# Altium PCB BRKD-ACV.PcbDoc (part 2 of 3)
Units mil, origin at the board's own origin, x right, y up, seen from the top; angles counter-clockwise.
Board outline 5708.66 x 3740.16 mil, 4 copper layers (L1-TOP, L2-GND, L3-PWR, L4-BOT), stack 61.722 mil thick; 171 components, 263 nets, 918 pads, 406 vias.
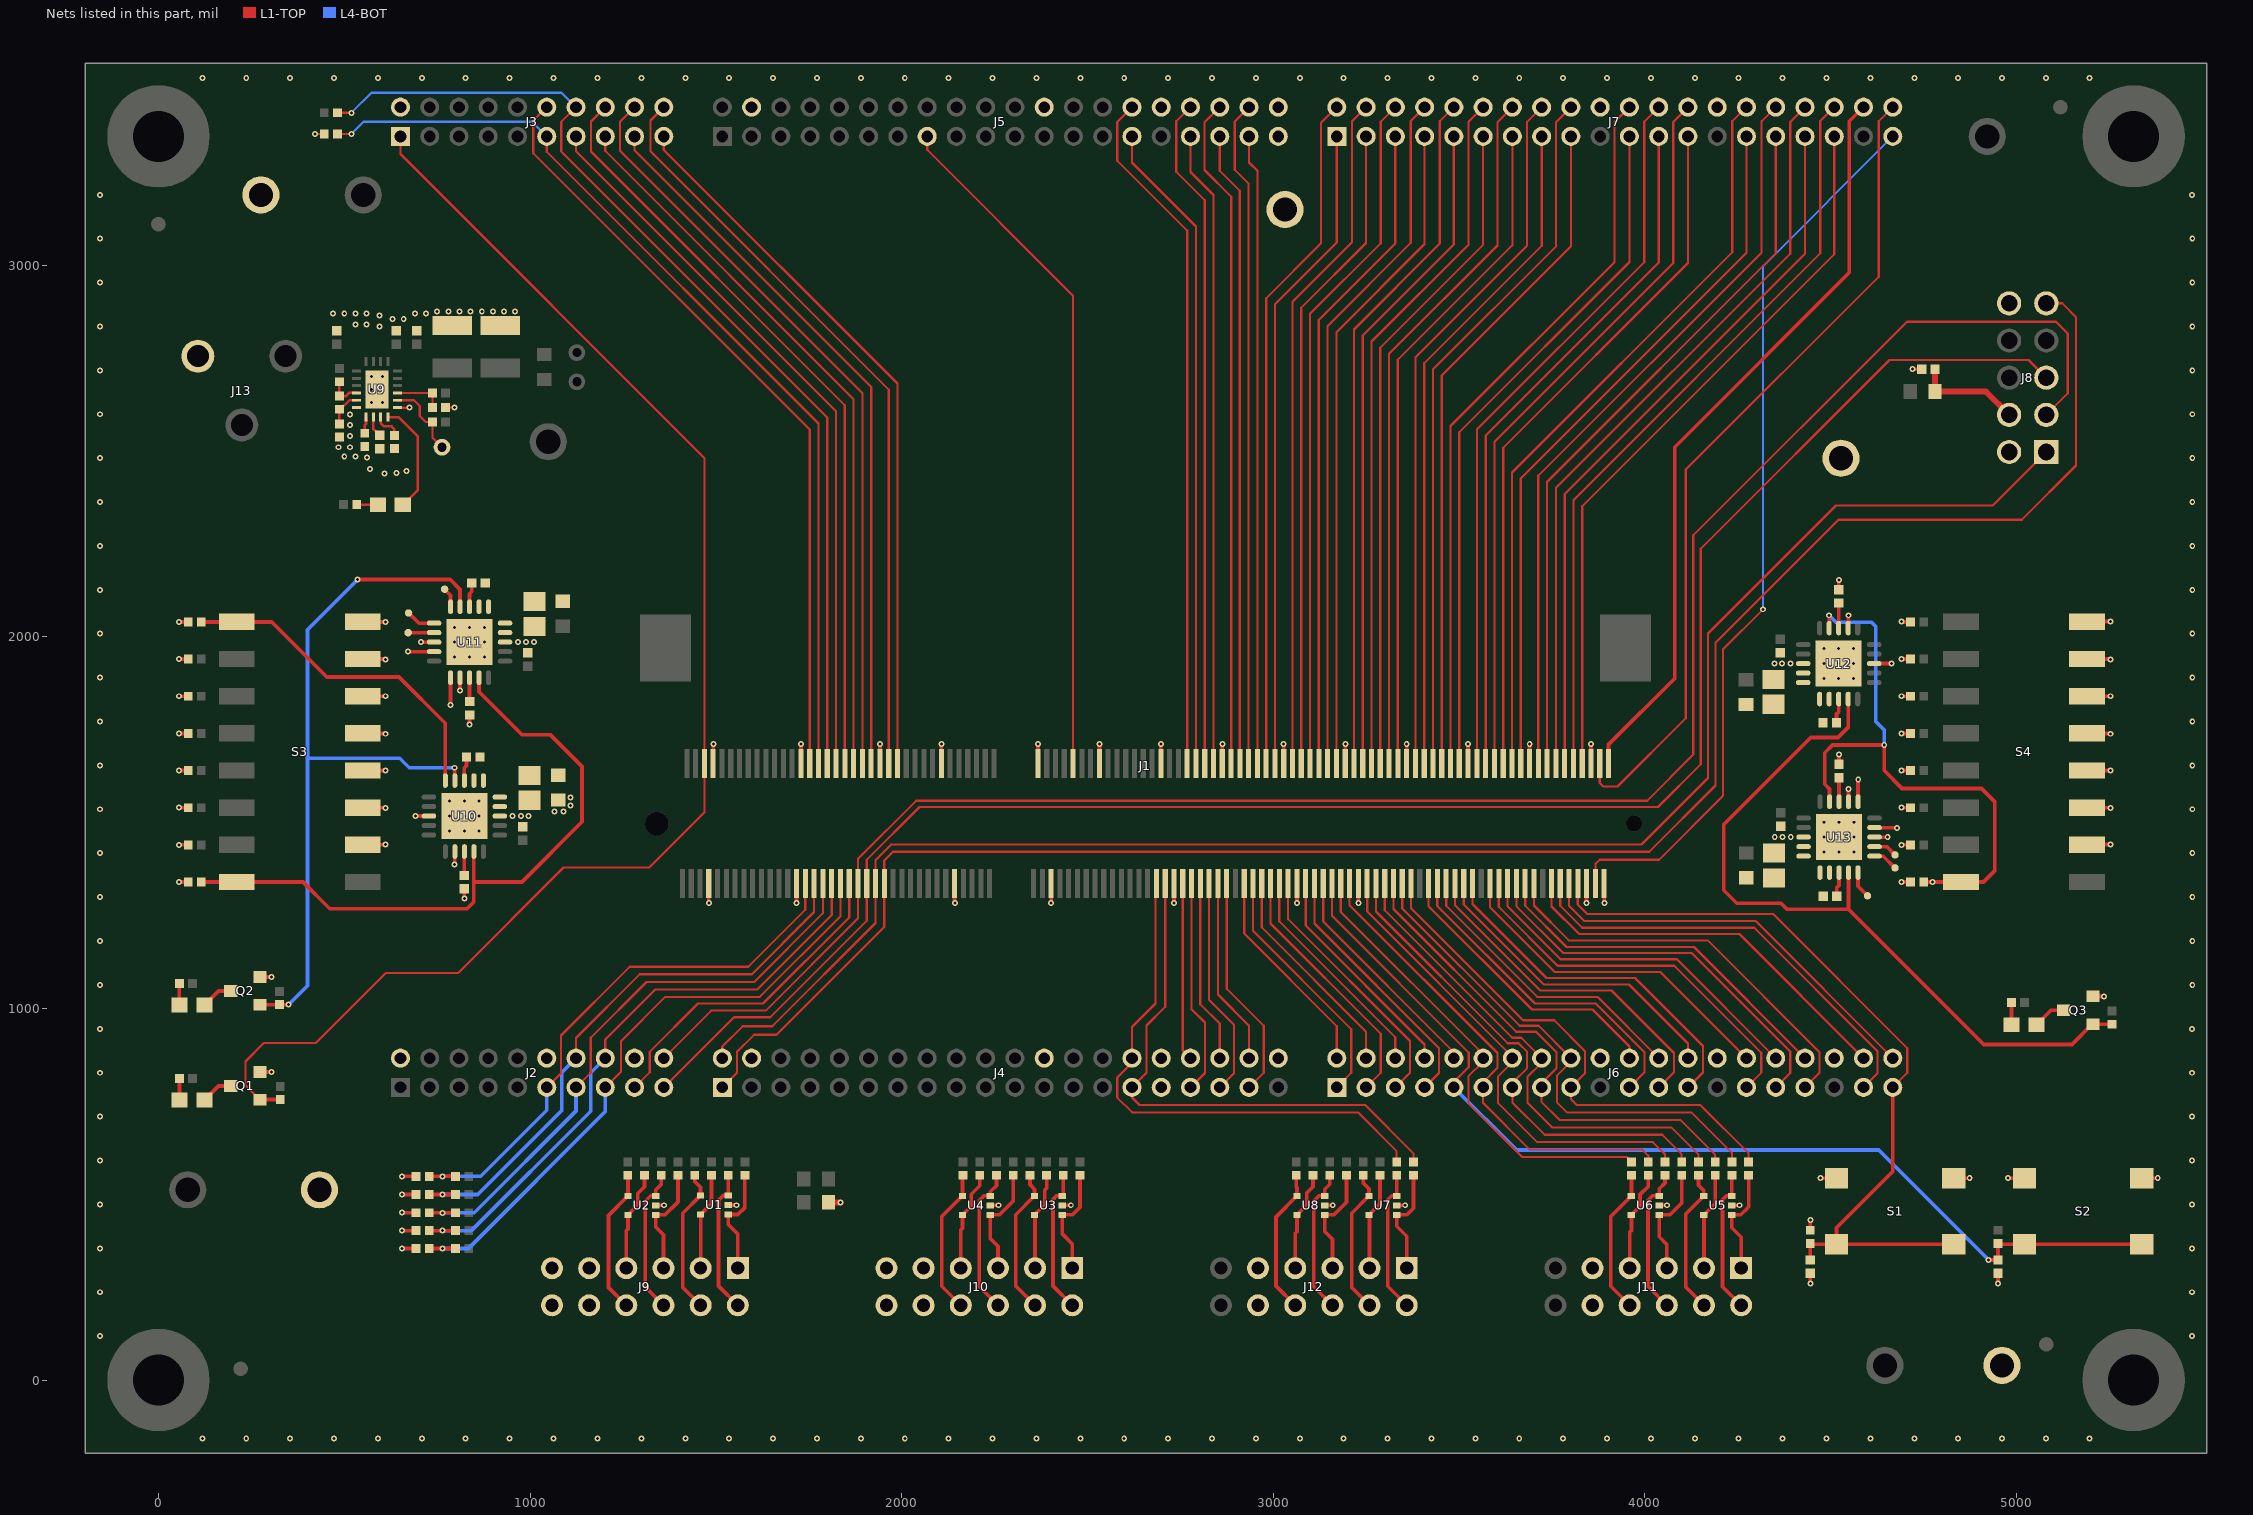
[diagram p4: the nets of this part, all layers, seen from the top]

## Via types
v1: diameter 16, hole 8, L1-TOP to L4-BOT, tented both sides, 406 vias

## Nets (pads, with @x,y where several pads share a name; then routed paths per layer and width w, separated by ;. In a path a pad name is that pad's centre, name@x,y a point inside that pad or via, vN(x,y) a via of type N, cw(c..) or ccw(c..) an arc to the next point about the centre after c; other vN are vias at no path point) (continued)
BANK3B_B23P: J1.82 J5.15 | length 1850.3
  L1-TOP w6: J5.15@2068.5,3346.46 2068.5,3310.5 2461.13,2917.87 J1.82@2461.13,1658.76
BANK3B_B24N: J1.101 J4.30 R39.1 | length 1460.6
  L1-TOP w5.5: J4.30@2619.69,866.14 2619.69,853.69 2580,814 2580,760 2620,720 3228,720 3332,616 R39.1@3332,586.72
  L1-TOP w6: J4.30@2619.69,866.14 2619.69,949.69 2683,1013 2683,1333.38 J1.101@2685.54,1335.92
BANK3B_B24P: J1.103 J4.29 R38.1 | length 1455.5
  L1-TOP w5.5: J4.29@2619.69,787.4 2619.69,760.31 2640,740 3247,740 3377,610 R38.1@3377,586.72
  L1-TOP w6: J4.29@2619.69,787.4 2659,826.72 2659,954 2709.17,1004.17 J1.103@2709.17,1335.92
BANK4A_B25N_RZQ_0: J1.109 J4.33 | length 579.5
  L1-TOP w6: J4.33@2777.17,787.4 2816,826.24 2816,962 2780.03,997.97 J1.109@2780.03,1335.92
BANK4A_B25P: J1.107 J4.34 | length 478.4
  L1-TOP w6: J1.107@2756.41,1335.92 2756.41,886.9 J4.34@2777.17,866.14
BANK4A_B26N: J1.110 J5.29 | length 1759
  L1-TOP w6: J5.29@2619.69,3346.46 2619.68,3276.31 2791.84,3104.16 J1.110@2791.84,1658.76
BANK4A_B26P: J1.108 J5.30 | length 1860.8
  L1-TOP w6: J5.30@2619.69,3425.2 2580,3385.51 2580,3281 2768.22,3092.78 J1.108@2768.22,1658.76
BANK4A_B27N: J1.112 J5.34 | length 1813.9
  L1-TOP w6: J5.34@2777.17,3425.2 2739,3387.03 2739,3251 2815.46,3174.54 J1.112@2815.46,1658.76
BANK4A_B27P: J1.114 J5.33 | length 1713.3
  L1-TOP w6: J5.33@2777.17,3346.46 2777.17,3250.83 2839.09,3188.91 J1.114@2839.09,1658.76
BANK4A_B28N: J1.113 J4.35 | length 591.9
  L1-TOP w6: J1.113@2827.28,1335.92 2827.28,1022.72 2894,956 2894,825.5 J4.35@2855.91,787.4
BANK4A_B28P: J1.111 J4.36 | length 491.4
  L1-TOP w6: J1.111@2803.65,1335.92 2803.65,1011.35 2855.91,959.09 J4.36@2855.91,866.14
BANK4A_B29N: J1.121 J6.2 | length 573
  L1-TOP w6: J1.121@2921.76,1335.92 2921.76,1201.24 3170.87,952.13 J6.2@3170.87,866.14
BANK4A_B29P: J1.123 J6.1 | length 674.3
  L1-TOP w6: J1.123@2945.39,1335.92 2945.39,1208.61 3210,944 3210,826.54 J6.1@3170.87,787.4
BANK4A_B30N: J1.115 J4.38 | length 504.5
  L1-TOP w6: J1.115@2850.9,1335.92 2850.9,1037.1 2934.65,953.35 J4.38@2934.65,866.14
BANK4A_B30P: J1.117 J4.37 | length 606
  L1-TOP w6: J1.117@2874.52,1335.92 2874.52,1052.48 2974,953 2974,826.76 J4.37@2934.65,787.4
BANK4A_B31N_CLK2N: J1.122 J5.38 | length 1798
  L1-TOP w6: J1.122@2933.57,1658.76 2933.57,3219.43 2896,3257 2896,3386.55 J5.38@2934.65,3425.2
BANK4A_B31P_CLK2P: J1.124 J5.37 | length 1697
  L1-TOP w6: J5.37@2934.65,3346.46 2934.65,3276.35 2957.2,3253.8 J1.124@2957.2,1658.76
BANK4A_B32N: J1.135 J6.8 | length 602.3
  L1-TOP w6: J1.135@3087.12,1335.92 3087.12,1222.88 3407.09,902.91 J6.8@3407.09,866.14
BANK4A_B32P: J1.137 J6.7 | length 703.5
  L1-TOP w6: J1.137@3110.74,1335.92 3110.74,1228.26 3446,893 3446,826.31 J6.7@3407.09,787.4
BANK4A_B33N: J1.143 J6.12 R49.1 | length 1270.5
  L1-TOP w5.5: J6.12@3564.57,866.14 3564.57,856.57 3525,817 3525,745 3670,600 3950.72,600 R49.1@3964,586.72
  L1-TOP w6: J1.143@3181.61,1335.92 3181.61,1259.3 3564.57,876.34 J6.12@3564.57,866.14
BANK4A_B33P: J1.145 J6.11 R48.1 | length 1291.5
  L1-TOP w5.5: J6.11@3564.57,787.4 3564.57,745.43 3690,620 3993,620 4009,604 R48.1@4009,586.72
  L1-TOP w6: J1.145@3205.23,1335.92 3205.23,1277.77 3603,880 3603,840 3564.57,801.57 J6.11@3564.57,787.4
BANK4A_B34N: J1.129 J6.6 | length 599.1
  L1-TOP w6: J1.129@3016.25,1335.92 3016.25,1234.75 3328.35,922.65 J6.6@3328.35,866.14
BANK4A_B34P: J1.131 J6.5 | length 700.9
  L1-TOP w6: J1.131@3039.87,1335.92 3039.87,1240.13 3368,912 3368,827.06 J6.5@3328.35,787.4
BANK4A_B35N: J1.118 J5.36 | length 1813.5
  L1-TOP w6: J5.36@2855.91,3425.2 2815,3384.29 2815,3256 2887,3184 2887,1659.43 J1.118@2886.33,1658.76
BANK4A_B35P: J1.120 J5.35 | length 1710.1
  L1-TOP w6: J5.35@2855.91,3346.46 2855.91,3254.09 2909.95,3200.05 J1.120@2909.95,1658.76
BANK4A_B36N: J1.136 J7.6 | length 1861.5
  L1-TOP w6: J1.136@3098.93,1658.76 3098.93,2868.93 3289,3059 3289,3385.85 J7.6@3328.35,3425.2
BANK4A_B36P: J1.138 J7.5 | length 1772.9
  L1-TOP w6: J1.138@3122.55,1658.76 3122.55,2852.55 3328.35,3058.35 J7.5@3328.35,3346.46
BANK4A_B37N: J1.139 J6.10 | length 615.4
  L1-TOP w6: J1.139@3134.36,1335.92 3134.36,1233.64 3485.83,882.17 J6.10@3485.83,866.14
BANK4A_B37P: C3.2 J1.141 J6.9 R19.1 S2.1 | length 2805.6
  L1-TOP w6: J1.141@3157.98,1335.92 3157.98,1249.02 3526,881 3526,842 3485.83,801.83 J6.9@3485.83,787.4
  L1-TOP w10: v1(4925,323) 4925.11,323.11 C3.2@4950,323.11 R19.1@4950,367.28 4951.87,365.42 S2.1@5021.52,365.42 S2.1@5336.48,365.42
  L4-BOT w10: J6.9@3485.83,787.4 3654.23,619 4629,619 v1(4925,323)
BANK4A_B38N: J1.152 J7.11 | length 1802.3
  L1-TOP w6: J1.152@3287.91,1658.76 3287.91,2777.91 3564.57,3054.57 J7.11@3564.57,3346.46
BANK4A_B38P: J1.150 J7.12 | length 1890.8
  L1-TOP w6: J1.150@3264.28,1658.76 3264.28,2794.28 3525,3055 3525,3385.63 J7.12@3564.57,3425.2
BANK4A_B39N_CLK3N: J1.126 J7.2 | length 1845.2
  L1-TOP w6: J1.126@2980.82,1658.76 2980.82,2910.82 3128,3058 3128,3382.33 J7.2@3170.87,3425.2
BANK4A_B39P_CLK3P: J1.128 J7.1 | length 1756.6
  L1-TOP w6: J1.128@3004.44,1658.76 3004.44,2894.44 3170.87,3060.87 J7.1@3170.87,3346.46
BANK4A_B40N: J1.149 J6.14 R45.1 | length 1295.1
  L1-TOP w5.5: J6.14@3643.31,866.14 3643.31,855.31 3605,817 3605,745 3710,640 4021,640 4054,607 R45.1@4054,586.72
  L1-TOP w6: J1.149@3252.47,1335.92 3252.47,1260.53 3643.31,869.69 J6.14@3643.31,866.14
BANK4A_B40P: J1.151 J6.13 R44.1 | length 1325.6
  L1-TOP w5.5: J6.13@3643.31,787.4 3643.31,746.69 3730,660 4047,660 4099,608 R44.1@4099,586.72
  L1-TOP w6: J1.151@3276.09,1335.92 3276.09,1260.91 3631,906 3660,906 3683,883 3683,839 3643.31,799.31 J6.13@3643.31,787.4
BANK4A_B41N: J1.153 J6.16 R41.1 | length 1332.6
  L1-TOP w5.5: J6.16@3722.05,866.14 3722.05,854.05 3684,816 3684,746 3750,680 4071,680 4144,607 R41.1@4144,586.72
  L1-TOP w6: J1.153@3299.72,1335.92 3299.72,1264.28 3643,921 3667.19,921 J6.16@3722.05,866.14
BANK4A_B41P: J1.155 J6.15 R40.1 | length 1362.3
  L1-TOP w5.5: J6.15@3722.05,787.4 3722.05,747.95 3770,700 4095,700 4189,606 R40.1@4189,586.72
  L1-TOP w6: J1.155@3323.34,1335.92 3323.34,1267.66 3654,937 3707,937 3762,882 3762,839 3722.05,799.05 J6.15@3722.05,787.4
BANK4A_B42N: J1.148 J7.9 | length 1789.3
  L1-TOP w6: J1.148@3240.66,1658.76 3240.66,2810.66 3485.83,3055.83 J7.9@3485.83,3346.46
BANK4A_B42P: J1.146 J7.10 | length 1877.8
  L1-TOP w6: J1.146@3217.04,1658.76 3217.04,2827.04 3448,3058 3448,3387.37 J7.10@3485.83,3425.2
BANK4A_B43N: J1.127 J6.3 | length 687.6
  L1-TOP w6: J1.127@2992.63,1335.92 2992.63,1228.37 3289,932 3289,826.8 J6.3@3249.61,787.4
BANK4A_B43P: J1.125 J6.4 | length 586
  L1-TOP w6: J1.125@2969.01,1335.92 2969.01,1217.99 3249.61,937.39 J6.4@3249.61,866.14
BANK4A_B44N: J1.154 J7.14 | length 1903.9
  L1-TOP w6: J1.154@3311.53,1658.76 3311.53,2761.53 3603,3053 3603,3384.89 J7.14@3643.31,3425.2
BANK4A_B44P: J1.156 J7.13 | length 1815.3
  L1-TOP w6: J1.156@3335.15,1658.76 3335.15,2745.15 3643.31,3053.31 J7.13@3643.31,3346.46
BANK4A_B45N: J1.162 J7.15 | length 1818.6
  L1-TOP w6: J1.162@3406.02,1658.76 3406.02,2736.02 3722.05,3052.05 J7.15@3722.05,3346.46
BANK4A_B45P: J1.160 J7.16 | length 1907.1
  L1-TOP w6: J1.160@3382.39,1658.76 3382.39,2752.39 3683,3053 3683,3386.15 J7.16@3722.05,3425.2
BANK4A_B46N: J1.142 J7.7 | length 1786
  L1-TOP w6: J1.142@3169.8,1658.76 3169.8,2819.8 3407.09,3057.09 J7.7@3407.09,3346.46
BANK4A_B46P: J1.140 J7.8 | length 1874.5
  L1-TOP w6: J1.140@3146.17,1658.76 3146.17,2836.17 3370,3060 3370,3388.11 J7.8@3407.09,3425.2
BANK4A_B47N: J1.132 J7.4 | length 1848.4
  L1-TOP w6: J1.132@3051.69,1658.76 3051.69,2901.69 3212,3062 3212,3387.59 J7.4@3249.61,3425.2
BANK4A_B47P: J1.134 J7.3 | length 1759.9
  L1-TOP w6: J1.134@3075.31,1658.76 3075.31,2885.31 3249.61,3059.61 J7.3@3249.61,3346.46
BANK4A_B48N: J1.159 J6.17 R36.1 | length 1400.8
  L1-TOP w5.5: J6.17@3800.79,787.4 3800.79,756.21 3817,740 4149,740 4279,610 R36.1@4279,586.72
  L1-TOP w6: J1.159@3370.58,1335.92 3370.58,1269.42 3672,968 3756,968 3839,885 3839,825.61 J6.17@3800.79,787.4
BANK4A_B48P: J1.157 J6.18 R37.1 | length 1374
  L1-TOP w5.5: J6.18@3800.79,866.14 3800.79,856.79 3763,819 3763,747 3790,720 4125,720 4234,611 R37.1@4234,586.72
  L1-TOP w6: J1.157@3346.96,1335.92 3346.96,1269.04 3663,953 3713.93,953 J6.18@3800.79,866.14
BANK5A_R1N_PR_REQUEST: J1.170 J7.21 | length 1877.3
  L1-TOP w6: J1.170@3500.5,1658.76 3500.5,2550.5 3958.27,3008.27 J7.21@3958.27,3346.46
BANK5A_R1P_RZQ_1: J1.168 J7.22 | length 1965.8
  L1-TOP w6: J1.168@3476.88,1658.76 3476.88,2566.88 3918,3008 3918,3384.93 J7.22@3958.27,3425.2
BANK5A_R2N_CRC_ERROR: J1.164 J7.18 | length 1920.2
  L1-TOP w6: J1.164@3429.64,1658.76 3429.64,2719.64 3761,3051 3761,3385.41 J7.18@3800.79,3425.2
BANK5A_R2P_INIT_DONE: J1.166 J7.17 | length 1831.7
  L1-TOP w6: J1.166@3453.26,1658.76 3453.26,2703.26 3800.79,3050.79 J7.17@3800.79,3346.46
BANK5A_R3N_CVP_CONFDONE: J1.169 J6.23 | length 922.1
  L1-TOP w6: J1.169@3488.69,1335.92 3488.69,1277.31 3718,1048 3910,1048 4078,880 4078,828.39 J6.23@4037.01,787.4
BANK5A_R3P_NCEO: J1.167 J6.24 | length 801.7
  L1-TOP w6: J1.167@3465.07,1335.92 3465.07,1275.93 3710,1031 3872.15,1031 J6.24@4037.01,866.14
BANK5A_R4N: J1.163 J6.22 | length 789.1
  L1-TOP w6: J1.163@3417.83,1335.92 3417.83,1275.17 3696,997 3859,997 3958.27,897.73 J6.22@3958.27,866.14
BANK5A_R4P: J1.165 J6.21 | length 892.4
  L1-TOP w6: J1.165@3441.45,1335.92 3441.45,1275.55 3704,1013 3868,1013 3999,882 3999,828.13 J6.21@3958.27,787.4
BANK5A_R5N_DEV_CLRN: J1.179 J6.29 | length 1041.4
  L1-TOP w6: J1.179@3606.8,1335.92 3606.8,1273.2 3765,1115 4079,1115 4313,881 4313,827.17 J6.29@4273.23,787.4
BANK5A_R5P_DEV_OE: J1.177 J6.30 | length 922.2
  L1-TOP w6: J1.177@3583.18,1335.92 3583.18,1271.82 3757,1098 4041.37,1098 J6.30@4273.23,866.14
BANK5A_R6N: J1.174 J7.24 | length 1969.1
  L1-TOP w6: J1.174@3547.75,1658.76 3547.75,2557.75 3998,3008 3998,3386.19 J7.24@4037.01,3425.2
BANK5A_R6P: J1.176 J7.23 | length 1880.6
  L1-TOP w6: J1.176@3571.37,1658.76 3571.37,2541.37 4037.01,3007.01 J7.23@4037.01,3346.46
BANK5A_R7N: J1.178 J7.26 | length 1982.1
  L1-TOP w6: J1.178@3594.99,1658.76 3594.99,2524.99 4076,3006 4076,3385.45 J7.26@4115.75,3425.2
BANK5A_R7P: J1.180 J7.25 | length 1893.6
  L1-TOP w6: J1.180@3618.61,1658.76 3618.61,2508.61 4115.75,3005.75 J7.25@4115.75,3346.46
BANK5A_R8N: J1.171 J6.26 | length 853.9
  L1-TOP w6: J1.171@3512.31,1335.92 3512.31,1279.69 3728,1064 3957,1064 4115.75,905.25 J6.26@4115.75,866.14
BANK5A_R8P: J1.173 J6.25 | length 961.4
  L1-TOP w6: J1.173@3535.94,1335.92 3535.94,1281.06 3735,1082 3973,1082 4156,899 4156,827.65 J6.25@4115.75,787.4
BANK5B_R9N_CLK6N: J1.184 J7.29 | length 1939.3
  L1-TOP w6: J1.184@3665.86,1658.76 3665.86,2425.86 4273.23,3033.23 J7.29@4273.23,3346.46
BANK5B_R9P_CLK6P: J1.182 J7.30 | length 2027.8
  L1-TOP w6: J1.182@3642.24,1658.76 3642.24,2442.24 4235,3035 4235,3386.97 J7.30@4273.23,3425.2
BANK5B_R10N: J1.181 J6.32 | length 952.1
  L1-TOP w6: J1.181@3630.42,1335.92 3630.42,1274.57 3773,1132 4086.11,1132 J6.32@4351.97,866.14
BANK5B_R10P: J1.183 J6.31 | length 1072.6
  L1-TOP w6: J1.183@3654.05,1335.92 3654.05,1274.95 3780,1149 4126,1149 4391,884 4391,826.43 J6.31@4351.97,787.4
BANK5B_R11N: J1.190 J7.31 | length 1942.5
  L1-TOP w6: J1.190@3736.72,1658.76 3736.72,2416.72 4351.97,3031.97 J7.31@4351.97,3346.46
BANK5B_R11P: J1.188 J7.32 | length 2031.1
  L1-TOP w6: J1.188@3713.1,1658.76 3713.1,2433.1 4314,3034 4314,3387.23 J7.32@4351.97,3425.2
BANK5B_R12N_BR_CLKOUTN: J1.193 J6.37 | length 1189.1
  L1-TOP w6: J1.193@3772.16,1335.92 3772.16,1275.84 3831,1217 4294,1217 4626,885 4626,825.21 J6.37@4588.19,787.4
BANK5B_R12P_BR_CLKOUTP: J1.191 J6.38 | length 1070.2
  L1-TOP w6: J1.191@3748.54,1335.92 3748.54,1274.46 3823,1200 4254.33,1200 J6.38@4588.19,866.14
BANK5B_R13N: J1.192 J7.34 | length 2044.1
  L1-TOP w6: J1.192@3760.35,1658.76 3760.35,2400.35 4391,3031 4391,3385.49 J7.34@4430.71,3425.2
BANK5B_R13P: J1.194 J7.33 | length 1955.6
  L1-TOP w6: J1.194@3783.97,1658.76 3783.97,2383.97 4430.71,3030.71 J7.33@4430.71,3346.46
BANK5B_R14N: J1.185 J6.34 | length 982.5
  L1-TOP w6: J1.185@3677.67,1335.92 3677.67,1276.33 3789,1165 4131.85,1165 J6.34@4430.71,866.14
BANK5B_R14P: J1.187 J6.33 | length 1102.3
  L1-TOP w6: J1.187@3701.29,1335.92 3701.29,1276.71 3795,1183 4169,1183 4470,882 4470,826.69 J6.33@4430.71,787.4
BANK5B_R15N: J1.196 J7.36 | length 2057.2
  L1-TOP w6: J1.196@3807.59,1658.76 3807.59,2367.59 4472,3032 4472,3387.75 J7.36@4509.45,3425.2
BANK5B_R15P: J1.198 J7.35 | length 1968.6
  L1-TOP w6: J1.198@3831.21,1658.76 3831.21,2351.21 4509.45,3029.45 J7.35@4509.45,3346.46
BANK5B_R16N: J1.195 J6.40 | length 1100.7
  L1-TOP w6: J1.195@3795.78,1335.92 3795.78,1276.22 3837,1235 4298.07,1235 J6.40@4666.93,866.14
BANK5B_R16P: C2.2 J1.197 J6.39 R18.1 S1.1 | length 2140
  L1-TOP w6: J1.197@3819.4,1335.92 3819.4,1279.6 3845,1254 4345,1254 4706,893 4706,826.47 J6.39@4666.93,787.4
  L1-TOP w10: C2.2@4445,323.11 R18.1@4445,367.28 4446.87,365.42 S1.1@4515.52,365.42 ; J6.39@4666.93,787.4 4666.93,560.93 4515.52,409.52 S1.1@4515.52,365.42 ; S1.1@4830.48,365.42 S1.1@4515.52,365.42
CONF_DONE: J1.30 J3.12 | length 2089.4
  L1-TOP w6: J3.12@1044.88,3425.2 1008.79,3389.11 1008.79,3301.21 1752.47,2557.53 J1.30@1752.47,1658.76
DATA0: J1.40 J3.15 | length 1964.5
  L1-TOP w6: J3.15@1202.36,3346.46 1202.36,3307.64 1870.58,2639.42 J1.40@1870.58,1658.76
DATA1: J1.42 J3.18 | length 2052.8
  L1-TOP w6: J3.18@1281.1,3425.2 1242,3386.09 1242,3308 1894.2,2655.8 J1.42@1894.2,1658.76
DATA2: J1.44 J3.17 | length 1951.4
  L1-TOP w6: J3.17@1281.1,3346.46 1281.1,3308.9 1917.83,2672.17 J1.44@1917.83,1658.76
DATA3: J1.48 J3.20 | length 2047
  L1-TOP w6: J3.20@1359.84,3425.2 1323.75,3389.11 1323.75,3306.25 1965.07,2664.93 J1.48@1965.07,1658.76
DCLK: J1.38 J3.16 | length 2065.2
  L1-TOP w6: J3.16@1202.36,3425.2 1164,3386.83 1164,3306 1846.96,2623.04 J1.38@1846.96,1658.76
DGND: C1.1 C2.1 C3.1 C4.2 C5.2 C6.1 C7.1 C8.1 C9.1 C10.1 C11.1 C12.1 C13.1 C16.1 C17.1 C18.1 C19.1 C20.1 C21.1 C24.1 C25.1 J1.7 J1.8 J1.27 J1.28 J1.46 J1.60 J1.63 J1.74 J1.77 J1.88 J1.102 J1.116 J1.130 J1.133 J1.144 J1.147 J1.158 J1.172 J1.186 J1.199 J1.200 J1.203 J2.2 J2.12 J2.18 J3.2 J4.4 J4.24 J4.32 J4.40 J5.4 J5.24 J5.32 J5.40 J6.20 J6.28 J6.36 J7.20 J7.28 J8.2 J8.10 J9.5 J9.11 J10.5 J10.11 J11.5 J11.11 J12.5 J12.11 J13.2 Q1.2 Q2.2 Q3.2 R7.1 R8.2 R9.1 R10.1 R11.2 R12.1 R58.1 R59.1 R60.1 R61.1 R66.1 R67.1 R68.1 R69.1 R70.1 R71.1 R72.1 R73.1 R78.1 R79.1 R80.1 R81.1 R82.1 R83.1 R84.1 R85.1 S1.2 S2.2 S3.10 S3.11 S3.12 S3.13 S3.14 S3.15 S3.16 S4.10 S4.11 S4.12 S4.13 S4.14 S4.15 S4.16 TP2.1 TP4.1 TP5.1 TP7.1 U1.2 U2.2 U3.2 U4.2 U5.2 U6.2 U7.2 U8.2 U9.1 U9.16 U9.PAD U10.0 U10.8 U10.12 U10.18 U11.0 U11.8 U11.9 U11.11 U11.12 U11.18 U12.0 U12.8 U12.12 U12.18 U13.0 U13.8 U13.9 U13.11 U13.12 U13.18 | length 3850.7
  L1-TOP w6: v1(421,3353) R7.1@446.28,3353 ; R58.1@772.72,2617 v1(797,2617)
  L1-TOP w7: U9.1@643.12,2616.79 675.79,2616.79 v1(676,2617)
  L1-TOP w10: v1(55.72,1340) R73.1@80,1340 ; v1(55.72,1440) R72.1@80,1440 ; v1(55.72,1540) R71.1@80,1540 ; v1(55.72,1640) R70.1@80,1640 ; v1(55.72,1740) R69.1@80,1740 ; v1(55.72,1840) R68.1@80,1840 ; v1(55.72,1940) R67.1@80,1940 ; v1(55.72,2040) R66.1@80,2040 ; Q1.2@273.37,828.77 303.6,828.77 v1(304,828.37) ; Q2.2@273.37,1084.4 303.6,1084.4 v1(304,1084) ; S3.10@549.5,1440 610,1440 v1(611,1441) ; S3.11@549.5,1540 610,1540 v1(611,1539) ; S3.12@549.5,1640 v1(611,1640) ; S3.13@549.5,1740 610,1740 v1(611,1739) ; S3.14@549.5,1840 v1(611,1840) ; S3.15@549.5,1940 610,1940 v1(611,1939) ; S3.16@549.5,2040 v1(611,2040) ; v1(655,354) R8.2@687.38,354 ; v1(655,402) R9.1@687.38,402 ; v1(655,451) 656,450 R10.1@687.38,450 ; v1(655,499) R11.2@687.38,499 ; v1(655,548) R12.1@687.38,548 ; v1(672,1960) U11.9@741.71,1959.98 ; v1(692.18,1517.57) U10.8@727.71,1517.57 ; v1(706.18,1985.57) U11.8@741.71,1985.57 ; v1(786,1816) U11.11@786,1890.1 ; v1(797.18,1387.57) 797.59,1387.98 U10.12@797.59,1422.1 ; v1(811.18,1855.57) 811.59,1855.98 U11.12@811.59,1890.1 ; v1(823.18,1295.57) C16.1@823.18,1321.46 ; v1(837.18,1763.57) C17.1@837.18,1789.46 ; U2.2@1338.4,470 1359.68,470 v1(1359.97,470.29) ; J1.7@1480.82,1335.92 1480.82,1284.18 v1(1481,1284) ; J1.8@1492.63,1658.76 1492.63,1710.63 v1(1493,1711) ; U1.2@1533.4,471 1554.26,471 v1(1554.97,470.29) ; v1(1717,1284) 1717.04,1284.04 J1.27@1717.04,1335.92 ; J1.28@1728.85,1658.76 1728.85,1710.85 v1(1729,1711) ; J1.46@1941.45,1658.76 1941.45,1710.45 v1(1942,1711) ; J1.60@2106.8,1658.76 2106.8,1710.8 v1(2107,1711) ; J1.63@2142.24,1335.92 2142.24,1284.76 v1(2143,1284) ; U4.2@2238.37,470.29 v1(2259.97,470.29) ; J1.74@2366.65,1658.76 2366.65,1710.65 v1(2367,1711) ; v1(2402,1284) 2402.08,1284.08 J1.77@2402.08,1335.92 ; U3.2@2433.37,470.29 v1(2454.97,470.29) ; J1.88@2532,1658.76 v1(2532,1711) ; J1.102@2697.35,1658.76 2697.35,1710.35 v1(2698,1711) ; J1.116@2862.71,1658.76 2862.71,1710.71 v1(2863,1711) ; v1(3028,1711) 3028.06,1710.94 J1.130@3028.06,1658.76 ; J1.133@3063.5,1335.92 3063.5,1284.5 v1(3064,1284) ; U8.2@3138.4,470 3159.68,470 v1(3159.97,470.29) ; J1.144@3193.42,1658.76 3193.42,1710.42 v1(3194,1711) ; J1.147@3228.85,1335.92 3228.85,1284.15 v1(3229,1284) ; U7.2@3333.37,470.29 v1(3354.97,470.29) ; J1.158@3358.77,1658.76 3358.77,1710.77 v1(3359,1711) ; v1(3524,1711) 3524.13,1710.87 J1.172@3524.13,1658.76 ; J1.186@3689.48,1658.76 3689.48,1710.48 v1(3690,1711) ; v1@3843.02,1284.02 J1.199@3843.02,1335.92 ; J1.200@3854.83,1658.76 3854.83,1710.83 v1(3855,1711) ; J1.203@3890.27,1335.92 3890.27,1284.73 v1(3891,1284) ; U6.2@4038.37,470.29 v1(4059.97,470.29) ; U5.2@4233.37,470.29 v1(4254.97,470.29) ; v1(4445,260) C2.1@4445,286.89 ; v1(4472,543) 4472.42,542.58 S1.2@4515.52,542.58 ; C24.1@4521.86,2126.98 v1(4521.86,2152.87) ; C25.1@4522.36,1656.98 v1(4522.36,1682.87) ; U12.12@4546.95,2023.34 4546.95,2057.46 v1(4547.36,2057.87) ; U13.12@4547.95,1556.34 4547.95,1590.46 v1(4548.36,1590.87) ; U13.11@4573.54,1556.34 4573.54,1615.54 v1(4574,1616) ; U12.8@4616.83,1927.87 v1(4663,1927.87) ; U13.8@4617.83,1460.87 v1(4653.36,1460.87) ; U13.9@4617.83,1486.46 4677.54,1486.46 v1(4678,1486) ; v1(4690.28,1340) R85.1@4714.57,1340 ; v1(4690.28,1440) R84.1@4714.57,1440 ; v1(4690.28,1540) R83.1@4714.57,1540 ; v1(4690.28,1640) R82.1@4714.57,1640 ; v1(4690.28,1740) R81.1@4714.57,1740 ; v1(4690.28,1840) R80.1@4714.57,1840 ; v1(4690.28,1940) R79.1@4714.57,1940 ; v1(4690.28,2041) 4691.28,2040 R78.1@4714.57,2040 ; v1(4719.54,2720) C1.1@4744.43,2720 ; S1.2@4830.48,542.58 4873.58,542.58 v1(4874,543) ; v1(4950,260) C3.1@4950,286.89 ; v1(4977,543) 4977.42,542.58 S2.2@5021.52,542.58 ; S4.10@5189.5,1440 5190.5,1441 v1(5253,1441) ; S4.11@5189.5,1540 5255,1540 v1@5256,1539 ; S4.12@5189.5,1640 v1(5253,1640) ; S4.13@5189.5,1740 5255,1740 v1@5256,1739 ; S4.14@5189.5,1840 v1(5253,1840) ; S4.15@5189.5,1940 5255,1940 v1@5256,1939 ; S4.16@5189.5,2040 5190.5,2041 v1(5253,2041) ; Q3.2@5205.37,1032.4 5205.77,1032 v1(5235,1032) ; v1@5255,1440 v1@5256,1441 ; S2.2@5336.48,542.58 5379.58,542.58 v1(5380,543)
  other v1: 1063.4,-157.89 1181.51,-157.89 1299.62,-157.89 1417.73,-157.89 1535.84,-157.89 1653.95,-157.89 1772.06,-157.89 1890.17,-157.89 2008.28,-157.89 2126.39,-157.89 2244.5,-157.89 2362.61,-157.89 2480.72,-157.89 2598.83,-157.89 2716.94,-157.89 2835.06,-157.89 2953.17,-157.89 3071.28,-157.89 3189.39,-157.89 3307.5,-157.89 3425.61,-157.89 3543.72,-157.89 3661.83,-157.89 3779.94,-157.89 3898.05,-157.89 4016.16,-157.89 4134.27,-157.89 4252.38,-157.89 4370.49,-157.89 4488.6,-157.89 4606.71,-157.89 4724.82,-157.89 4842.93,-157.89 4961.04,-157.89 5079.15,-157.89 118.11,-157.48 236.22,-157.48 354.33,-157.48 472.44,-157.48 590.55,-157.48 708.66,-157.48 826.77,-157.48 944.88,-157.48 5196.85,-157.48 -157.48,118.11 5472.44,118.11 -157.48,236.22 5472.44,236.22 -157.48,354.33 5472.44,354.33 -157.48,472.44 5472.44,472.44 -157.48,590.55 5472.44,590.55 -157.48,708.66 5472.44,708.66 -157.48,826.77 5472.44,826.77 -157.48,944.88 5472.44,944.88 -157.07,1063.4 5472.85,1063.4 -157.07,1181.51 5472.85,1181.51 3843,1284 -157.07,1299.62 5472.85,1299.62 -157.07,1417.73 5472.85,1417.73 4482.36,1420.87 4522.36,1420.87 4562.36,1420.87 4349.36,1460.87 4370.36,1460.87 4392.36,1460.87 4482.36,1460.87 4522.36,1460.87 4562.36,1460.87 783.18,1477.57 823.18,1477.57 863.18,1477.57 4482.36,1500.87 4522.36,1500.87 4562.36,1500.87 783.18,1517.57 823.18,1517.57 863.18,1517.57 953.18,1517.57 975.18,1517.57 996.18,1517.57 -157.07,1535.84 5472.85,1535.84 5253,1539 783.18,1557.57 823.18,1557.57 863.18,1557.57 -157.07,1653.95 5472.85,1653.95 5253,1739 -157.07,1772.06 5472.85,1772.06 4481.36,1887.87 4521.36,1887.87 4561.36,1887.87 -157.07,1890.17 5472.85,1890.17 4348.36,1927.87 4369.36,1927.87 4391.36,1927.87 4481.36,1927.87 4521.36,1927.87 4561.36,1927.87 5253,1939 797.18,1945.57 837.18,1945.57 877.18,1945.57 4481.36,1967.87 4521.36,1967.87 4561.36,1967.87 797.18,1985.57 837.18,1985.57 877.18,1985.57 967.18,1985.57 989.18,1985.57 1010.18,1985.57 -157.07,2008.28 5472.85,2008.28 797.18,2025.57 837.18,2025.57 877.18,2025.57 -157.07,2126.39 5472.85,2126.39 -157.07,2244.5 5472.85,2244.5 -157.07,2362.61 5472.85,2362.61 608,2439 640,2441 667,2446 569,2452 -157.07,2480.72 5472.85,2480.72 561,2482 500,2485 530,2485 484,2510 515,2510 515,2540 515,2570 515,2598 -157.07,2598.83 5472.85,2598.83 573,2631 603,2631 573,2666 603,2666 573,2701 603,2701 -157.07,2716.94 5472.85,2716.94 -157.07,2835.06 595,2835 5472.85,2835.06 530,2840 560,2840 630,2855 660,2855 595,2865 470,2870 500,2870 530,2870 560,2870 690,2870 720,2870 750,2875 780,2875 810,2875 840,2875 870,2875 900,2875 930,2875 960,2875 -157.07,2953.17 5472.85,2953.17 -157.07,3071.28 5472.85,3071.28 -157.48,3188.98 5472.44,3188.98 118.11,3503.94 236.22,3503.94 354.33,3503.94 472.44,3503.94 590.55,3503.94 708.66,3503.94 826.77,3503.94 944.88,3503.94 1063.4,3503.94 1181.51,3503.94 1299.62,3503.94 1417.73,3503.94 1535.84,3503.94 1653.95,3503.94 1772.06,3503.94 1890.17,3503.94 2008.28,3503.94 2126.39,3503.94 2244.5,3503.94 2362.61,3503.94 2480.72,3503.94 2598.83,3503.94 2716.94,3503.94 2835.06,3503.94 2953.17,3503.94 3071.28,3503.94 3189.39,3503.94 3307.09,3503.94 3425.61,3503.94 3543.72,3503.94 3661.83,3503.94 3779.94,3503.94 3898.05,3503.94 4016.16,3503.94 4134.27,3503.94 4252.38,3503.94 4370.49,3503.94 4488.6,3503.94 4606.71,3503.94 4724.82,3503.94 4842.93,3503.94 4961.04,3503.94 5079.15,3503.94 5196.85,3503.94
EEPROM_SCL: J1.202 J7.40 | length 2238.8
  L1-TOP w6: J1.202@3878.46,1658.76 3878.46,1606.54 3888,1597 3926,1597 4110,1781 4110,2450 4629,2969 4629,3387.27 J7.40@4666.93,3425.2
EEPROM_SDA: J1.201 J7.39 | length 2435.7
  L1-TOP w5.5: J1.201@3866.65,1335.92 3866.65,1388.65 3878,1400 4038,1400 4210,1572 4210,1966 v1(4318,2074)
  L4-BOT w5.5: v1(4318,2074) 4318,2997.53 J7.39@4666.93,3346.46
EEPROM_VCC: J1.204 J7.38 | length 2050.6
  L1-TOP w10: J1.204@3902.08,1658.76 3902.08,1710.08 4080,1888 4080,2510 4550,2980 4550,3387.01 J7.38@4588.19,3425.2
FPGA_TCK: J1.45 J4.2 J8.1 | length 4583.4
  L1-TOP w6: J4.2@1517.32,866.14 1517.32,897.32 1572,952 1652,952 1929.64,1229.64 J1.45@1929.64,1335.92 1929.64,1398.64 1972,1441 3991,1441 4170,1620 4170,2009 4514,2353 4935.8,2353 J8.1@5080,2497.2
FPGA_TDI: J1.47 J4.1 J8.9 | length 5192.9
  L1-TOP w6: J4.1@1517.32,787.4 1557,827.08 1557,883 1603,929 1663,929 1953.26,1219.26 J1.47@1953.26,1335.92 1953.26,1398.26 1976.5,1421.5 4011.5,1421.5 4190,1600 4190,1984 4521,2315 5014,2315 5160,2461 5160,2860 5122.8,2897.2 J8.9@5080,2897.2
FPGA_TDO: J1.41 J2.20 J8.3 | length 5294.5
  L1-TOP w6: J2.20@1359.84,866.14 1487.7,994 1634,994 1882.39,1242.39 J1.41@1882.39,1335.92 1882.39,1402.39 2039,1559 4006,1559 4130,1683 4130,2273 4705,2848 5106,2848 5138,2816 5138,2655.2 J8.3@5080,2597.2
FPGA_TMS: J1.43 J2.19 J8.5 | length 4986.6
  L1-TOP w6: J2.19@1359.84,787.4 1548.44,976 1646,976 1906.02,1236.02 J1.43@1906.02,1335.92 1906.02,1400.02 2048,1542 4035,1542 4150,1657 4150,2237 4658,2745 5032.2,2745 J8.5@5080,2697.2
MSEL0: J1.29 J2.11 R5.2 R12.2 | length 1498.4
  L1-TOP w6: J2.11@1044.88,787.4 1083,825.52 1083,927 1268,1112 1587,1112 1740.66,1265.66 J1.29@1740.66,1335.92
  L1-TOP w10: R12.2@734.62,548 R5.2@793.38,548
  L4-BOT w10: v1(764,548) 867,548 1044.88,725.88 J2.11@1044.88,787.4
MSEL1: J1.31 J2.14 R4.1 R11.1 | length 1542.6
  L1-TOP w6: J2.14@1123.62,866.14 1123.62,920.62 1295,1092 1597,1092 1764.28,1259.28 J1.31@1764.28,1335.92
  L1-TOP w10: R11.1@734.62,499 R4.1@793.38,499
  L4-BOT w10: v1(764,499) 859,499 1085,725 1085,827.52 J2.14@1123.62,866.14
MSEL2: J1.33 J2.13 R3.2 R10.2 | length 1589
  L1-TOP w6: J2.13@1123.62,787.4 1163,826.78 1163,921 1313,1071 1603,1071 1787.91,1255.91 J1.33@1787.91,1335.92
  L1-TOP w10: R10.2@734.62,450 R3.2@793.38,450
  L4-BOT w10: v1(764,450) 850,450 1123.62,723.62 J2.13@1123.62,787.4
MSEL3: J1.35 J2.16 R2.1 R9.2 | length 1632.8
  L1-TOP w6: J2.16@1202.36,866.14 1202.36,916.36 1337,1051 1611,1051 1811.53,1251.53 J1.35@1811.53,1335.92
  L1-TOP w10: R9.2@734.62,402 R2.1@793.38,402
  L4-BOT w10: v1(764,402) 842,402 1163,723 1163,826.78 J2.16@1202.36,866.14
MSEL4: J1.37 J2.15 R1.1 R8.1 | length 1674.2
  L1-TOP w6: J2.15@1202.36,787.4 1245.01,830.05 1245.01,912.01 1364,1031 1618,1031 1835.15,1248.15 J1.37@1835.15,1335.92
  L1-TOP w10: R8.1@734.62,354 R1.1@793.38,354
  L4-BOT w10: v1(764,354) 834,354 1202.36,722.36 J2.15@1202.36,787.4
NCE: J1.32 J3.11 R7.2 | length 2577.9
  L1-TOP w6: R7.2@487.62,3353 v1(519,3353) ; J3.11@1044.88,3346.46 1044.88,3305.12 1776.09,2573.91 J1.32@1776.09,1658.76
  L4-BOT w6: v1(519,3353) 552,3386 1005.34,3386 J3.11@1044.88,3346.46
NCONFIG: J1.34 J3.14 R6.1 | length 2753.8
  L1-TOP w6: R6.1@487.62,3410 v1(519,3410) ; J3.14@1123.62,3425.2 1084,3385.57 1084,3306 1799.72,2590.28 J1.34@1799.72,1658.76
  L4-BOT w6: v1(519,3410) 573,3464 1084.82,3464 J3.14@1123.62,3425.2
NCSO_DATA4: J1.50 J3.19 | length 1948.2
  L1-TOP w6: J3.19@1359.84,3346.46 1359.84,3310.16 1988.69,2681.31 J1.50@1988.69,1658.76
NetC1_2: C1.2 J8.4 R17.1 | length 285.2
  L1-TOP w10: C1.2@4780.65,2720 C1.2@4781,2719.65
  L1-TOP w16: C1.2@4781,2719.65 R17.1@4781,2660 4917.2,2660 J8.4@4980,2597.2
NetC9_2: C9.2 U9.18 | length 56.1
  L1-TOP w7: U9.18@578.16,2591.2 578.16,2558.95 C9.2@595,2542.11
NetC11_2: C11.2 C14.2 R63.1 U10.1 U10.2 U10.19 U10.20
NetC13_2: C13.2 C15.2 R64.1 U11.1 U11.2 U11.19 U11.20
NetC14_1: C14.1 U10.3 | length 66
  L1-TOP w10: U10.3@823.18,1613.05 823.18,1647.57 829.07,1653.46 C14.1@829.07,1676.57
NetC15_1: C15.1 U11.3 | length 66
  L1-TOP w10: U11.3@837.18,2081.05 837.18,2115.57 843.07,2121.46 C15.1@843.07,2144.57
NetC16_2: C16.2 U10.13 | length 64.4
  L1-TOP w10: C16.2@823.18,1357.69 U10.13@823.18,1422.1
NetC17_2: C17.2 U11.13 | length 64.4
  L1-TOP w10: C17.2@837.18,1825.69 U11.13@837.18,1890.1
NetC19_2: C19.2 C22.2 R75.1 U12.1 U12.2 U12.19 U12.20
NetC21_2: C21.2 C23.2 R76.1 U13.1 U13.2 U13.19 U13.20
NetC22_1: C22.1 U12.3 | length 66
  L1-TOP w10: C22.1@4515.47,1768.87 4515.47,1791.98 4521.36,1797.87 U12.3@4521.36,1832.39
NetC23_1: C23.1 U13.3 | length 66
  L1-TOP w10: C23.1@4516.47,1301.87 4516.47,1324.98 4522.36,1330.87 U13.3@4522.36,1365.39
NetC24_2: C24.2 U12.13 | length 64.4
  L1-TOP w10: U12.13@4521.36,2023.34 C24.2@4521.36,2087.76
NetC25_2: C25.2 U13.13 | length 64.4
  L1-TOP w10: U13.13@4522.36,1556.34 C25.2@4522.36,1620.76
NetD1_1: D1.1 R15.1 | length 57.6
  L1-TOP w10: D1.1@56.54,753.37 R15.1@56.54,811
NetD1_2: D1.2 Q1.3 | length 86.9
  L1-TOP w10: D1.2@123.46,753.37 161.46,791.37 Q1.3@194.63,791.37
NetD2_1: D2.1 R57.1 | length 57.2
  L1-TOP w7: R57.1@533.72,2356 534.72,2355 D2.1@590.54,2355
NetD2_2: D2.2 U9.20 | length 302.9
  L1-TOP w7: U9.20@617.53,2591.2 645.8,2591.2 698,2539 698,2395.54 D2.2@657.46,2355
NetD3_1: D3.1 R62.1 | length 58.1
  L1-TOP w10: R62.1@56.28,1067 56.28,1009.25 D3.1@56.54,1009
NetD3_2: D3.2 Q2.3 | length 86.9
  L1-TOP w10: D3.2@123.46,1009 161.46,1047 Q2.3@194.63,1047
NetD4_1: D4.1 R74.1 | length 60.1
  L1-TOP w10: R74.1@4986.28,1016 4986.54,1015.75 D4.1@4986.54,956
NetD4_2: D4.2 Q3.3 | length 89.3
  L1-TOP w10: D4.2@5053.46,956 5092.46,995 Q3.3@5126.63,995
NetQ2_1: Q2.1 R65.1 U10.4 U11.4 | length 2073.3
  L1-TOP w10: Q2.1@273.37,1009.6 325.31,1009.6 R65.1@326,1010.28 326.28,1010 v1(350,1010) ; v1(536,2154) 785,2154 811.59,2127.41 U11.4@811.59,2081.05 ; v1(797.18,1647.57) 797.59,1647.17 U10.4@797.59,1613.05
  L4-BOT w10: v1(350,1010) 401,1061 401,1671 ; v1(536,2154) 401,2019 401,1671 ; v1(797.18,1647.57) 674.57,1647.57 649.15,1673 403,1673 401,1671
NetQ3_1: Q3.1 R77.1 U12.4 U13.4 | length 2034.4
  L1-TOP w10: U12.4@4546.95,1832.39 4547.46,1831.89 4547.46,1757 4519.46,1729 4446,1729 4212,1495 4212,1318 4247,1283 4366,1283 4382,1267 4547.95,1267 ; U13.4@4547.95,1365.39 4547.95,1267 ; R77.1@5257,957.28 5203.28,957.28 5149,903 4911.95,903 4547.95,1267
NetR53_1: R53.1 TP13.1 U9.2 | length 212.9
  L1-TOP w6: U9.2@643.12,2636.47 687.53,2636.47 703,2621 703,2594 719,2578 R53.1@737.28,2578 737.28,2535.72 TP13.1@763,2510
NetR54_1: R54.1 R58.2 U9.3 | length 133.2
  L1-TOP w6: U9.3@643.12,2656.16 737.13,2656.16 R54.1@737.28,2656 R58.2@737.28,2617
NetR55_1: R55.1 R56.2 U9.14 | length 87.9
  L1-TOP w7: R55.1@487,2686.28 R56.2@487,2647.72 504.72,2647.72 513.16,2656.16 U9.14@532.88,2656.16
NetR56_1: R56.1 R59.2 U9.15 | length 95.5
  L1-TOP w7: R59.2@487,2572.72 R56.1@487,2612.28 490.28,2612.28 514.47,2636.47 U9.15@532.88,2636.47
NetR60_2: R60.2 U9.19 | length 76.6
  L1-TOP w7: U9.19@597.84,2591.2 597.84,2575.16 607,2566 627,2566 635,2558 R60.2@635,2541.72
NetR61_2: R61.2 U9.17 | length 44.9
  L1-TOP w7: R61.2@555,2547.72 555,2569 558.47,2572.47 U9.17@558.47,2591.2
NetTP14_1: TP14.1 U11.5 | length 53.6
  L1-TOP w10: TP14.1@770,2128 786,2112 U11.5@786,2081.05
NetTP15_1: TP15.1 U11.6 | length 80
  L1-TOP w10: TP15.1@673,2064 700.24,2036.76 U11.6@741.71,2036.76
NetTP16_1: TP16.1 U11.7 | length 69.8
  L1-TOP w10: TP16.1@672,2011 672.17,2011.17 U11.7@741.71,2011.17
NetTP17_1: TP17.1 U13.5 | length 72.9
  L1-TOP w10: U13.5@4573.54,1365.39 4573.54,1328.46 TP17.1@4599,1303
NetTP18_1: TP18.1 U13.6 | length 68.3
  L1-TOP w10: U13.6@4617.83,1409.69 4641.32,1409.69 TP18.1@4673,1378
NetTP19_1: TP19.1 U13.7 | length 64.4
  L1-TOP w10: U13.7@4617.83,1435.28 4650.72,1435.28 TP19.1@4673,1413
NSTATUS: J1.36 J3.13 | length 1977.5
  L1-TOP w6: J3.13@1123.62,3346.46 1123.62,3306.38 1823.34,2606.66 J1.36@1823.34,1658.76
POD1_IO1: J9.1 R20.2 U1.1 | length 294.4
  L1-TOP w10: J9.1@1559,301 1559,393 1533.4,418.6 U1.1@1533.4,445.41 1559.08,445.41 1578,464.33 R20.2@1578,551.28
POD1_IO2: J9.2 R24.2 U1.5 | length 262.6
  L1-TOP w10: J9.2@1459,301 1459,445.01 U1.5@1458.6,445.41 1488,474.81 R24.2@1488,551.28
POD1_IO3: J9.3 R28.2 U2.1 | length 298
  L1-TOP w10: J9.3@1359,301 1359,391 1338.4,411.6 U2.1@1338.4,444.41 1363.08,444.41 1398,479.33 R28.2@1398,551.28
POD1_IO4: J9.4 R32.2 U2.5 | length 270.6
  L1-TOP w10: J9.4@1259,301 1259,402 1263.6,406.6 U2.5@1263.6,444.41 1290,470.81 1290,502 1308,520 R32.2@1308,551.28
POD1_IO7: J9.7 R21.2 U1.3 | length 391
  L1-TOP w10: R21.2@1533,551.28 1533.4,550.88 U1.3@1533.4,496.59 1519.59,496.59 1507,484 1507,253 J9.7@1559,201
POD1_IO8: J9.8 R25.2 U1.4 | length 396.3
  L1-TOP w10: R25.2@1443,551.28 1443,534 1458.6,518.4 U1.4@1458.6,496.59 1411,448.99 1411,249 J9.8@1459,201
POD1_IO9: J9.9 R29.2 U2.3 | length 396.5
  L1-TOP w10: R29.2@1353,551.28 1353,526 1338.4,511.4 U2.3@1338.4,495.59 1324.59,495.59 1310,481 1310,250 J9.9@1359,201
POD1_IO10: J9.10 R33.2 U2.4 | length 392.2
  L1-TOP w10: J9.10@1259,201 1211,249 1211,442.99 U2.4@1263.6,495.59 1263.6,550.69 R33.2@1263,551.28
POD2_IO1: J10.1 R22.2 U3.1 | length 296.8
  L1-TOP w10: J10.1@2459,301 2459,366 2432.4,392.6 U3.1@2432.4,444.41 2459.41,444.41 2480,465 R22.2@2480,551.28
POD2_IO2: J10.2 R26.2 U3.5 | length 264.3
  L1-TOP w10: J10.2@2359,301 2359,443.01 U3.5@2357.6,444.41 2385,471.81 2385,511 2390,516 R26.2@2390,551.28
POD2_IO3: J10.3 R30.2 U4.1 | length 298.8
  L1-TOP w10: J10.3@2259,301 2259,360 2238.4,380.6 U4.1@2238.4,444.41 2263.08,444.41 2300,481.33 R30.2@2300,551.28
POD2_IO4: J10.4 R34.2 U4.5 | length 271.4
  L1-TOP w10: J10.4@2159,301 2159,404 2163.6,408.6 U4.5@2163.6,444.41 2187,467.81 2187,500 2210,523 R34.2@2210,551.28
POD2_IO7: J10.7 R23.2 U3.3 | length 392.7
  L1-TOP w10: R23.2@2435,551.28 2435,498.19 U3.3@2432.4,495.59 2416.59,495.59 2407,486 2407,253 J10.7@2459,201
POD2_IO8: J10.8 R27.2 U3.4 | length 398
  L1-TOP w10: R27.2@2345,551.28 2345,526 2357.6,513.4 U3.4@2357.6,495.59 2307,444.99 2307,253 J10.8@2359,201
POD2_IO9: J10.9 R31.2 U4.3 | length 399.9
  L1-TOP w10: R31.2@2255,551.28 2255,523 2238.4,506.4 U4.3@2238.4,495.59 2221.59,495.59 2209,483 2209,251 J10.9@2259,201
POD2_IO10: J10.10 R35.2 U4.4 | length 395
  L1-TOP w10: J10.10@2159,201 2108,252 2108,439.99 U4.4@2163.6,495.59 2163.6,549.88 R35.2@2165,551.28
POD3_IO1: J12.1 R38.2 U7.1 | length 295.6
  L1-TOP w10: J12.1@3359,301 3359,387 3332.4,413.6 U7.1@3332.4,444.41 3359.41,444.41 3377,462 R38.2@3377,551.28
POD3_IO2: J12.2 R42.2 U7.5 | length 263
  L1-TOP w10: J12.2@3259,301 3259,443.01 U7.5@3257.6,444.41 3287,473.81 R42.2@3287,551.28
POD3_IO3: J12.3 R46.2 U8.1 | length 297.5
  L1-TOP w10: J12.3@3159,301 3159,379 3138.4,399.6 U8.1@3138.4,444.41 3163.08,444.41 3197,478.33 R46.2@3197,551.28
POD3_IO4: J12.4 R50.2 U8.5 | length 270.2
  L1-TOP w10: J12.4@3059,301 3059,395 3063.6,399.6 U8.5@3063.6,444.41 3090,470.81 3090,503 3107,520 R50.2@3107,551.28
POD3_IO7: J12.7 R39.2 U7.3 | length 389.8
  L1-TOP w10: R39.2@3332,551.28 3332.4,550.88 U7.3@3332.4,495.59 3318.59,495.59 3308,485 3308,252 J12.7@3359,201
POD3_IO8: J12.8 R43.2 U7.4 | length 395.9
  L1-TOP w10: R43.2@3242,551.28 3242,530 3257.6,514.4 U7.4@3257.6,495.59 3211,448.99 3211,249 J12.8@3259,201
POD3_IO9: J12.9 R47.2 U8.3 | length 398.1
  L1-TOP w10: R47.2@3152,551.28 3152,527 3138.4,513.4 U8.3@3138.4,495.59 3122.59,495.59 3109,482 3109,251 J12.9@3159,201
POD3_IO10: J12.10 R51.2 U8.4 | length 395.9
  L1-TOP w10: J12.10@3059,201 3007,253 3007,438.99 U8.4@3063.6,495.59 3063.6,517.4 3062,519 R51.2@3062,551.28
POD4_IO1: J11.1 R36.2 U5.1 | length 294.2
  L1-TOP w10: J11.1@4259,301 4259,384 4233.4,409.6 U5.1@4233.4,444.41 4258.08,444.41 4275.47,461.8 4275.47,462.47 4279,466 R36.2@4279,551.28
POD4_IO2: J11.2 R40.2 U5.5 | length 263
  L1-TOP w10: J11.2@4159,301 4159,444.01 U5.5@4158.6,444.41 4189,474.81 R40.2@4189,551.28
POD4_IO3: J11.3 R44.2 U6.1 | length 300.9
  L1-TOP w10: J11.3@4059,301 4059,365 4038.4,385.6 U6.1@4038.4,444.41 4067.41,444.41 4099,476 R44.2@4099,551.28
POD4_IO4: J11.4 R48.2 U6.5 | length 271
  L1-TOP w10: J11.4@3959,301 3959,398 3963.6,402.6 U6.5@3963.6,444.41 3987,467.81 3987,499 4009,521 R48.2@4009,551.28
POD4_IO7: J11.7 R37.2 U5.3 | length 389.4
  L1-TOP w10: R37.2@4234,551.28 4233.4,550.69 U5.3@4233.4,495.59 4219.59,495.59 4209,485 4209,251 J11.7@4259,201
POD4_IO8: J11.8 R41.2 U5.4 | length 396.8
  L1-TOP w10: R41.2@4144,551.28 4144,524 4158.6,509.4 U5.4@4158.6,495.59 4110,446.99 4110,250 J11.8@4159,201
POD4_IO9: J11.9 R45.2 U6.3 | length 400.9
  L1-TOP w10: R45.2@4054,551.28 4054,530 4038.4,514.4 U6.3@4038.4,495.59 4020.59,495.59 4008,483 4008,252 J11.9@4059,201
POD4_IO10: J11.10 R49.2 U6.4 | length 394.6
  L1-TOP w10: J11.10@3959,201 3908,252 3908,439.99 U6.4@3963.6,495.59 3963.6,550.88 R49.2@3964,551.28
PWR1_EN: R73.2 S3.8 U10.14 U11.14 | length 1812.1
  L1-TOP w10: R73.2@115.43,1340 S3.8@210.5,1340 389,1340 461,1268 830,1268 848.77,1286.77 848.77,1340 ; U10.14@848.77,1422.1 848.77,1340 ; U11.14@862.77,1890.1 862.77,1852.23 979,1736 1055,1736 1140,1651 1140,1502 978,1340 848.77,1340
PWR2_EN: R85.2 S4.8 U12.14 U13.14 | length 1597.7
  L1-TOP w10: v1(4495.36,2057.87) 4495.77,2057.46 U12.14@4495.77,2023.34 ; U13.14@4496.77,1556.34 4496.77,1590.46 4484,1603.23 4484,1688 4505,1709 v1(4644,1709) 4644,1640 4692,1592 4906,1592 4941,1557 4941,1370 4911,1340 S4.8@4850.5,1340 v1(4774,1340) R85.2@4750,1340
  L4-BOT w10: v1(4495.36,2057.87) 4514.23,2039 4610,2039 4621,2028 4621,1772 4644,1749 v1(4644,1709)
PWRGOOD: J1.6 J3.1 Q1.1 R16.1 | length 3845.2
  L1-TOP w6: Q1.1@273.37,753.97 234,793.34 234,857.37 283.63,907 423,907 611.5,1095.5 806.5,1095.5 1090,1379 1321,1379 1469.01,1527.01 J1.6@1469.01,1658.76 1469.01,2480.99 651.18,3298.82 J3.1@651.18,3346.46
  L1-TOP w10: Q1.1@273.37,753.97 274.06,754.65 R16.1@328,754.65
VCCBAT: J1.39 J2.17 | length 890.3
  L1-TOP w6: J2.17@1281.1,787.4 1322,828.3 1322,883 1452,1013 1627,1013 1858.77,1244.77 J1.39@1858.77,1335.92
VCCIO1: J1.105 J4.31 J5.39 J9.6 J9.12 J10.6 J10.12 R13.1 R18.2 R63.2 TP3.1 | length 110.8
  L1-TOP w10: J1.105@2732.79,1335.92 2732.79,1284.21 v1(2733,1284) ; R18.2@4445,402.72 v1(4445,430)
  L1-TOP w16: R13.1@1803.46,478 v1(1835,478)
  other v1: 1066,1530 1090,1530 1109,1546 1109,1568
VCCIO1_50MV: R66.2 S3.1 U10.5 | length 923.6
  L1-TOP w10: R66.2@115.43,2040 S3.1@210.5,2040 305,2040 453,1892 647,1892 772,1767 U10.5@772,1613.05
